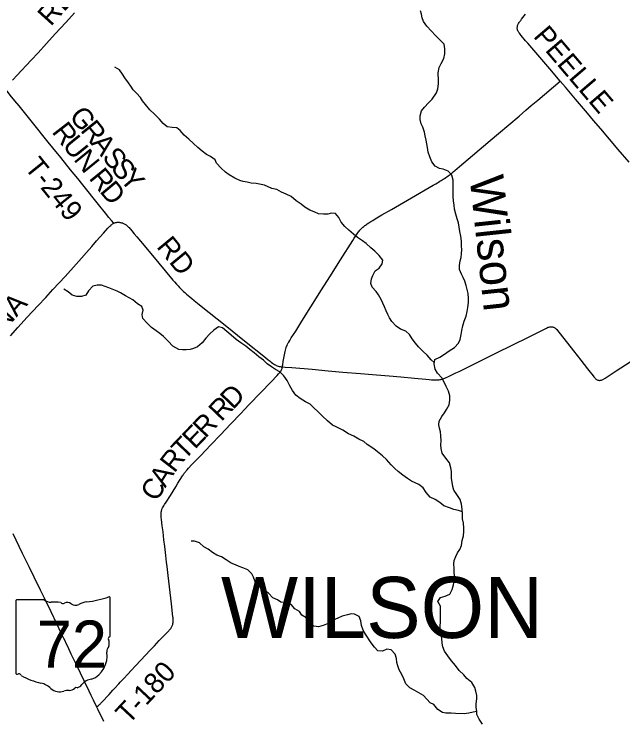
# Model space of a CAD drawing. Extents: x 1442749 to 1756758, y 235267 to 677782.
# Drawn here: x 1630533 to 1639504, y 554957 to 565368 of the extents above; entities that cross this region are included whole.
import ezdxf

# ---------------------------------------------------------------- set-up
doc = ezdxf.new("R2010")
doc.units = 0
for name, color, linetype in [('GM_X_County_Road', 7, 'Continuous'), ('GM_X_County_Road_Text', 7, 'Continuous'), ('GM_X_Minor_River', 7, 'Continuous'), ('GM_X_Minor_River_Text', 7, 'Continuous'), ('GM_X_State_Location', 7, 'Continuous'), ('GM_X_State_Route', 7, 'Continuous'), ('GM_X_State_Shield', 7, 'Continuous'), ('GM_X_Township_Road', 7, 'Continuous'), ('GM_X_Township_Road_Text', 7, 'Continuous'), ('GM_X_Township_Text', 7, 'Continuous')]:
    doc.layers.add(name, color=color, linetype=linetype)

msp = doc.modelspace()

# ---------------------------------------------------------------- linework, layer by layer
at = {"layer": 'GM_X_County_Road'}
for points in [[(1630480, 560630), (1630587, 560750), (1630725, 560902), (1630885, 561075), (1630998, 561196), (1631105, 561312), (1631283, 561503), (1631447, 561687), (1631676, 561946), (1631748, 562027), (1631851, 562143), (1631916, 562214), (1631936, 562236), (1631945, 562246), (1631956, 562256), (1631964, 562263), (1631973, 562271), (1631982, 562278), (1631991, 562283), (1632000, 562288)], [(1632000, 562288), (1632009, 562292), (1632018, 562296), (1632029, 562298), (1632040, 562300), (1632053, 562302), (1632066, 562302), (1632080, 562302), (1632092, 562300), (1632104, 562299), (1632117, 562296), (1632128, 562292), (1632137, 562289), (1632146, 562286), (1632155, 562281), (1632165, 562276), (1632174, 562270), (1632184, 562263), (1632191, 562257), (1632199, 562250), (1632209, 562241), (1632218, 562232), (1632227, 562223), (1632237, 562212), (1632247, 562201), (1632267, 562177), (1632303, 562134), (1632341, 562089), (1632395, 562024), (1632546, 561842), (1632665, 561698), (1632854, 561472), (1632874, 561449), (1632896, 561424), (1632926, 561390), (1632949, 561364), (1632970, 561342), (1632990, 561321), (1633007, 561304), (1633028, 561284), (1633048, 561266), (1633073, 561244), (1633098, 561224), (1633122, 561203), (1633151, 561180), (1633187, 561151), (1633234, 561112), (1633291, 561067), (1633645, 560785), (1633929, 560557), (1634236, 560310), (1634278, 560275), (1634304, 560254), (1634321, 560241), (1634340, 560227), (1634355, 560217), (1634370, 560207), (1634384, 560200), (1634397, 560194), (1634411, 560188), (1634426, 560183), (1634438, 560179), (1634453, 560176), (1634470, 560174), (1634485, 560172)], [(1634485, 560172), (1634528, 560168), (1634627, 560161), (1634925, 560136), (1635160, 560115), (1635379, 560096), (1635635, 560075), (1635873, 560055), (1636062, 560038), (1636232, 560024), (1636432, 560007), (1636598, 559991), (1636651, 559986), (1636684, 559982), (1636709, 559980), (1636731, 559979), (1636750, 559979), (1636766, 559979), (1636781, 559980), (1636798, 559982), (1636812, 559985), (1636823, 559987), (1636837, 559991), (1636849, 559995), (1636863, 560000), (1636880, 560007), (1636900, 560016), (1636925, 560027), (1636956, 560041), (1636994, 560059), (1637042, 560082), (1637091, 560106), (1637150, 560135), (1637305, 560211), (1637640, 560380), (1638112, 560611), (1638377, 560744), (1638392, 560751), (1638404, 560756), (1638415, 560759), (1638428, 560762), (1638438, 560763), (1638449, 560763), (1638458, 560763), (1638468, 560761), (1638478, 560758), (1638487, 560755), (1638493, 560752), (1638500, 560748), (1638507, 560743), (1638515, 560737), (1638523, 560729), (1638530, 560721), (1638542, 560709), (1638562, 560684), (1638634, 560590), (1638777, 560406), (1638885, 560270), (1638982, 560145), (1639004, 560117), (1639064, 560039), (1639075, 560026), (1639085, 560013), (1639094, 560004), (1639101, 559997), (1639108, 559991), (1639117, 559985), (1639125, 559981), (1639133, 559977), (1639141, 559975), (1639148, 559974), (1639158, 559973), (1639166, 559973), (1639174, 559974), (1639181, 559976), (1639191, 559978), (1639200, 559982), (1639207, 559986), (1639216, 559991), (1639226, 559997), (1639234, 560002), (1639242, 560007), (1639403, 560111), (1639679, 560290)]]:
    msp.add_lwpolyline(points, dxfattribs=at)
at = {"layer": 'GM_X_Minor_River'}
for points in [[(1636789, 564392), (1636782, 564504), (1636799, 564584), (1636826, 564640), (1636867, 564712), (1636880, 564782), (1636878, 564855), (1636869, 564925), (1636805, 564988), (1636742, 565053), (1636678, 565122), (1636614, 565189), (1636565, 565261), (1636547, 565312), (1636536, 565366), (1636522, 565418)], [(1636724, 560234), (1636679, 560276), (1636621, 560345), (1636562, 560400), (1636494, 560467), (1636450, 560521), (1636401, 560586), (1636357, 560649), (1636305, 560697), (1636229, 560728), (1636161, 560773), (1636097, 560842), (1636066, 560892), (1636038, 560943), (1636017, 560999), (1635991, 561056), (1635966, 561112), (1635942, 561163), (1635904, 561231), (1635867, 561282), (1635807, 561347), (1635791, 561401), (1635800, 561467), (1635821, 561519), (1635854, 561585), (1635910, 561625), (1635959, 561691), (1635968, 561745), (1635912, 561814), (1635849, 561874), (1635789, 561925), (1635721, 561990), (1635665, 562027), (1635595, 562076), (1635535, 562126), (1635464, 562185), (1635404, 562240), (1635354, 562303), (1635319, 562371), (1635267, 562430), (1635211, 562435), (1635158, 562423), (1635090, 562422), (1635016, 562428), (1634956, 562457), (1634891, 562480), (1634817, 562525), (1634762, 562571), (1634690, 562616), (1634614, 562683), (1634544, 562714), (1634472, 562745), (1634402, 562784), (1634330, 562798), (1634275, 562823), (1634225, 562847), (1634151, 562862), (1634099, 562871), (1634025, 562879), (1633968, 562892), (1633910, 562903), (1633858, 562917), (1633784, 562954), (1633704, 563003), (1633650, 563042), (1633582, 563100), (1633517, 563171), (1633495, 563224), (1633425, 563273), (1633369, 563299), (1633303, 563350), (1633238, 563405), (1633174, 563464), (1633108, 563525), (1633038, 563586), (1632981, 563652), (1632929, 563691), (1632861, 563696), (1632790, 563708), (1632728, 563755), (1632675, 563822), (1632601, 563893), (1632535, 563960), (1632468, 564035), (1632424, 564089), (1632394, 564140), (1632337, 564203), (1632289, 564255), (1632255, 564306), (1632220, 564358), (1632166, 564429), (1632132, 564482), (1632085, 564546), (1632017, 564585)], [(1637124, 558150), (1637108, 558216), (1637055, 558291), (1637013, 558354), (1637000, 558410), (1636986, 558474), (1636979, 558529), (1636979, 558579), (1636978, 558633), (1636968, 558687), (1636949, 558760), (1636896, 558828), (1636842, 558899), (1636827, 558970), (1636821, 559022), (1636826, 559084), (1636820, 559154), (1636817, 559213), (1636803, 559269), (1636790, 559319), (1636798, 559372), (1636837, 559441), (1636876, 559493), (1636903, 559545), (1636942, 559613), (1636954, 559681), (1636955, 559746), (1636936, 559812), (1636902, 559881), (1636865, 559955), (1636835, 560010), (1636771, 560079), (1636736, 560139), (1636721, 560216), (1636733, 560280), (1636804, 560317), (1636877, 560361), (1636946, 560408), (1637023, 560458), (1637082, 560519), (1637108, 560575), (1637123, 560650), (1637132, 560710), (1637147, 560776), (1637163, 560846), (1637192, 560918), (1637209, 560986), (1637220, 561048), (1637227, 561118), (1637231, 561179), (1637222, 561253), (1637210, 561313), (1637195, 561370), (1637175, 561432), (1637150, 561489), (1637124, 561539), (1637097, 561606), (1637095, 561666), (1637108, 561732), (1637119, 561784), (1637127, 561840), (1637132, 561898), (1637128, 561957), (1637125, 562023), (1637118, 562099), (1637100, 562168), (1637091, 562228), (1637080, 562292), (1637060, 562351), (1637041, 562423), (1637021, 562494), (1637016, 562554), (1637006, 562616), (1637003, 562683), (1637005, 562853), (1637004, 562924), (1636982, 562994), (1636928, 563055), (1636856, 563082), (1636802, 563094), (1636740, 563127), (1636687, 563192), (1636657, 563264), (1636636, 563333), (1636624, 563405), (1636615, 563457), (1636605, 563512), (1636592, 563576), (1636578, 563629), (1636555, 563701), (1636533, 563753), (1636516, 563816), (1636516, 563870), (1636537, 563944), (1636578, 563998), (1636637, 564062), (1636694, 564115), (1636757, 564207), (1636776, 564267), (1636787, 564341), (1636789, 564392)], [(1637138, 558035), (1637079, 558058), (1637013, 558072), (1636948, 558095), (1636866, 558126), (1636806, 558175), (1636736, 558216), (1636666, 558254), (1636603, 558319), (1636561, 558392), (1636495, 558439), (1636443, 558463), (1636389, 558488), (1636331, 558529), (1636263, 558577), (1636194, 558632), (1636142, 558673), (1636090, 558730), (1636022, 558807), (1635961, 558863), (1635889, 558920), (1635833, 558963), (1635737, 559030), (1635685, 559071), (1635611, 559106), (1635537, 559151), (1635461, 559187), (1635379, 559238), (1635327, 559265), (1635277, 559287), (1635225, 559312), (1635153, 559379), (1635078, 559448), (1635008, 559515), (1634950, 559568), (1634894, 559620), (1634826, 559657), (1634747, 559704), (1634683, 559755), (1634635, 559824), (1634594, 559894), (1634556, 559971), (1634507, 560038), (1634449, 560098), (1634387, 560135), (1634325, 560174), (1634263, 560219), (1634207, 560269), (1634141, 560322), (1634068, 560381), (1634006, 560430), (1633950, 560477), (1633874, 560524), (1633804, 560574), (1633732, 560639), (1633667, 560694), (1633605, 560745), (1633543, 560760), (1633478, 560714), (1633419, 560658), (1633358, 560595), (1633303, 560527), (1633236, 560469), (1633177, 560442), (1633127, 560428), (1633066, 560421), (1633012, 560421), (1632960, 560428), (1632874, 560477), (1632804, 560552), (1632733, 560617), (1632681, 560663), (1632627, 560704), (1632557, 560751), (1632495, 560816), (1632432, 560886), (1632418, 560943), (1632433, 561009), (1632415, 561059), (1632351, 561100), (1632282, 561161), (1632228, 561190), (1632172, 561220), (1632102, 561261), (1632052, 561288), (1631978, 561316), (1631927, 561337), (1631875, 561357), (1631823, 561374), (1631755, 561373), (1631692, 561359), (1631631, 561293), (1631592, 561226), (1631526, 561206), (1631456, 561207), (1631387, 561230), (1631330, 561276), (1631266, 561317)], [(1637433, 554910), (1637385, 554981), (1637354, 555049), (1637350, 555100), (1637343, 555154), (1637343, 555206), (1637350, 555280), (1637353, 555331), (1637337, 555397), (1637320, 555447), (1637276, 555520), (1637204, 555583), (1637161, 555634), (1637089, 555700), (1637039, 555775), (1636978, 555842), (1636926, 555913), (1636877, 555986), (1636851, 556050), (1636842, 556104), (1636838, 556175), (1636825, 556225), (1636809, 556299), (1636810, 556356), (1636815, 556410), (1636817, 556472), (1636814, 556532), (1636815, 556649), (1636777, 556715), (1636816, 556773), (1636887, 556793), (1636954, 556822), (1636990, 556892), (1637009, 556960), (1637018, 557018), (1637021, 557093), (1637017, 557149), (1637016, 557205), (1637012, 557267), (1637017, 557319), (1637040, 557377), (1637068, 557431), (1637103, 557483), (1637128, 557541), (1637135, 557613), (1637155, 557684), (1637158, 557748), (1637161, 557798), (1637155, 557868), (1637142, 557935), (1637141, 558005), (1637135, 558075), (1637124, 558150)], [(1637351, 555094), (1637300, 555086), (1637233, 555069), (1637163, 555063), (1637038, 555064), (1636974, 555069), (1636897, 555072), (1636847, 555080), (1636775, 555127), (1636718, 555196), (1636666, 555221), (1636614, 555277), (1636566, 555330), (1636496, 555371), (1636428, 555410), (1636362, 555442), (1636305, 555503), (1636277, 555576), (1636248, 555642), (1636206, 555711), (1636189, 555767), (1636175, 555819), (1636166, 555874), (1636146, 555940), (1636088, 556003), (1636026, 556012), (1635960, 555982), (1635893, 555987), (1635843, 556043), (1635794, 556108), (1635711, 556235), (1635679, 556292), (1635650, 556361), (1635644, 556429), (1635617, 556497), (1635549, 556530), (1635499, 556533), (1635446, 556521), (1635369, 556500), (1635305, 556470), (1635236, 556439), (1635159, 556391), (1635085, 556362), (1635018, 556342), (1634948, 556351), (1634884, 556418), (1634830, 556479), (1634772, 556515), (1634739, 556566), (1634671, 556607), (1634615, 556671), (1634537, 556696), (1634465, 556707), (1634413, 556738), (1634343, 556772), (1634283, 556837), (1634209, 556888), (1634129, 556949), (1634080, 557020), (1634062, 557072), (1634038, 557125), (1633975, 557181), (1633901, 557212), (1633848, 557233), (1633796, 557255), (1633732, 557282), (1633660, 557331), (1633591, 557374), (1633522, 557398), (1633454, 557437), (1633393, 557486), (1633329, 557523), (1633263, 557578), (1633191, 557606), (1633140, 557605)]]:
    msp.add_lwpolyline(points, dxfattribs=at)
at = {"layer": 'GM_X_State_Route'}
msp.add_lwpolyline([(1631855, 554948), (1631766, 555131), (1631749, 555167), (1631703, 555261), (1631670, 555329), (1631639, 555394), (1631511, 555660), (1631443, 555802), (1631376, 555941), (1631323, 556053), (1631301, 556098), (1631283, 556135), (1631267, 556169), (1631232, 556240), (1631163, 556385), (1631078, 556562), (1630980, 556763), (1630922, 556881), (1630829, 557072), (1630760, 557217), (1630658, 557423), (1630607, 557526), (1630520, 557710)], dxfattribs=at)
at = {"layer": 'GM_X_State_Shield'}
for p, q in [((1631948, 556213), (1631948, 556765)), ((1630556, 556721), (1630556, 555664)), ((1630978, 556739), (1630570, 556739)), ((1631948, 556213), (1631948, 556213))]:
    msp.add_line(p, q, dxfattribs=at)
for centre, radius, start, end in [((1631452, 558180), 1476, 275.8445, 288.9065), ((1631933, 556768), 15.5, 351.8621, 97.738), ((1630572, 556723), 16.1, 98.1301, 188.1301), ((1631075, 556862), 156, 231.6195, 271.1119), ((1631126, 556146), 562, 80.4867, 94.9883), ((1631254, 556729), 45.1, 219.7921, 297.1024), ((1631320, 556607), 93.8, 54.4667, 119.1411), ((1631441, 556774), 113, 233.8562, 294.8282), ((1631641, 556417), 297, 97.3462, 120.7689), ((1631945, 556172), 24, 107.944, 210.337), ((1631792, 556102), 144, 340.033, 23.6496), ((1631932, 556211), 16.6, 289.6038, 7.7341), ((1632004, 555981), 105, 136.8065, 186.9296), ((1631535, 555911), 369, 292.3089, 8.9858), ((1630572, 555662), 16.3, 171.9584, 258.3066), ((1630575, 555770), 124, 267.339, 280.6039), ((1630600, 555604), 44.8, 29.7484, 93.2717), ((1631165, 556553), 1066, 240.4129, 257.1985), ((1631691, 555368), 202, 94.4031, 142.5768), ((1630847, 555190), 334, 47.1842, 75.836), ((1631208, 555598), 212, 230.7004, 286.2918), ((1631346, 555519), 113, 268.777, 315.5493), ((1631448, 555417), 31.8, 65.7517, 132.6484), ((1631435, 555562), 119, 282.8732, 323.2771), ((1631331, 555233), 174, 85.6951, 111.2099)]:
    msp.add_arc(centre, radius, start, end, dxfattribs=at)
at = {"layer": 'GM_X_Township_Road'}
for points in [[(1630510, 564395), (1630520, 564404), (1630574, 564462), (1630783, 564688), (1630885, 564799), (1631010, 564934), (1631140, 565077), (1631293, 565244), (1631423, 565387)], [(1638582, 564380), (1638527, 564442), (1638455, 564527), (1638103, 564938), (1638071, 564976), (1638003, 565055), (1637988, 565073), (1637978, 565086), (1637971, 565095), (1637965, 565105), (1637960, 565112), (1637957, 565120), (1637954, 565125), (1637952, 565132), (1637950, 565140), (1637949, 565147), (1637948, 565155), (1637947, 565164), (1637948, 565172), (1637949, 565182), (1637950, 565189), (1637953, 565200), (1637957, 565210), (1637961, 565219), (1637967, 565230), (1637975, 565243), (1637981, 565253), (1637988, 565263), (1637998, 565276), (1638010, 565292), (1638029, 565316), (1638071, 565369)], [(1634485, 560172), (1634491, 560204), (1634499, 560250), (1634516, 560350), (1634521, 560375), (1634526, 560398), (1634532, 560419), (1634537, 560439), (1634543, 560456), (1634549, 560471), (1634555, 560487), (1634563, 560504), (1634573, 560524), (1634582, 560538), (1634594, 560559), (1634606, 560579), (1634618, 560598), (1634683, 560700), (1634774, 560845), (1634907, 561055), (1635065, 561305), (1635185, 561497), (1635342, 561747), (1635522, 562033), (1635545, 562068), (1635565, 562099), (1635578, 562118), (1635587, 562131), (1635598, 562147), (1635607, 562159), (1635618, 562172), (1635628, 562184), (1635637, 562194), (1635647, 562205), (1635657, 562215), (1635671, 562228), (1635686, 562240), (1635701, 562252), (1635711, 562260), (1635724, 562269), (1635737, 562278), (1635762, 562295), (1635789, 562312), (1635818, 562330), (1635854, 562352), (1635952, 562409), (1636094, 562492), (1636448, 562698), (1636650, 562815), (1636706, 562848), (1636746, 562870), (1636772, 562885), (1636788, 562895), (1636806, 562905), (1636826, 562917), (1636842, 562927), (1636856, 562936), (1636876, 562949), (1636893, 562961), (1636910, 562973), (1636927, 562985), (1636943, 562997), (1636957, 563007), (1636971, 563019), (1636987, 563031), (1637005, 563046), (1637028, 563066), (1637095, 563123), (1637287, 563286), (1637547, 563508), (1637669, 563612), (1637973, 563867), (1638073, 563952), (1638153, 564020), (1638251, 564102), (1638582, 564380)], [(1639595, 563188), (1639434, 563375), (1639305, 563527), (1639178, 563677), (1639072, 563803), (1638980, 563910), (1638806, 564115), (1638658, 564291), (1638582, 564380)], [(1632000, 562288), (1631967, 562330), (1631931, 562373), (1631882, 562434), (1631776, 562564), (1631544, 562853), (1631470, 562945), (1631366, 563076), (1631221, 563254), (1631103, 563400), (1631037, 563481), (1630996, 563533), (1630844, 563722), (1630606, 564015), (1630544, 564092), (1630476, 564175), (1630434, 564227), (1630424, 564239), (1630416, 564248), (1630407, 564257), (1630395, 564269)], [(1631749, 555167), (1631763, 555176), (1631775, 555184), (1631783, 555190), (1631791, 555197), (1631799, 555204), (1631806, 555212), (1631826, 555233), (1631934, 555348), (1631989, 555409), (1632014, 555435), (1632076, 555503), (1632096, 555525), (1632138, 555571), (1632212, 555649), (1632254, 555695), (1632329, 555774), (1632467, 555923), (1632537, 555997), (1632600, 556063), (1632672, 556139), (1632768, 556239), (1632782, 556254), (1632811, 556284), (1632819, 556293), (1632828, 556303), (1632836, 556312), (1632841, 556319), (1632849, 556330), (1632854, 556339), (1632859, 556348), (1632863, 556357), (1632867, 556368), (1632870, 556377), (1632872, 556386), (1632874, 556395), (1632875, 556402), (1632876, 556414), (1632877, 556428), (1632877, 556441), (1632876, 556456), (1632875, 556473), (1632873, 556489), (1632850, 556681), (1632802, 557098), (1632787, 557229), (1632780, 557294), (1632769, 557392), (1632753, 557525), (1632741, 557626), (1632727, 557743), (1632716, 557831), (1632704, 557925), (1632701, 557955), (1632699, 557971), (1632698, 557990), (1632698, 558003), (1632699, 558019), (1632701, 558033), (1632703, 558045), (1632705, 558054), (1632708, 558064), (1632712, 558074), (1632716, 558084), (1632722, 558096), (1632729, 558109), (1632737, 558124), (1632751, 558146), (1632772, 558180), (1632835, 558279), (1632915, 558407), (1632946, 558457), (1633014, 558566), (1633022, 558578), (1633030, 558589), (1633038, 558601), (1633046, 558612), (1633055, 558623), (1633062, 558632), (1633070, 558642), (1633076, 558649), (1633083, 558657), (1633102, 558679), (1633153, 558734), (1633284, 558868), (1633429, 559019), (1633581, 559178), (1633721, 559326), (1633877, 559490), (1633925, 559539), (1634002, 559620), (1634322, 559953), (1634408, 560045), (1634431, 560069), (1634443, 560083), (1634450, 560092), (1634457, 560100), (1634462, 560108), (1634467, 560115), (1634470, 560122), (1634474, 560130), (1634477, 560137), (1634481, 560148), (1634483, 560159), (1634485, 560172)]]:
    msp.add_lwpolyline(points, dxfattribs=at)

# ---------------------------------------------------------------- texts
at = {"layer": 'GM_X_County_Road_Text'}
for s, rotation, p in [('RD', 309.4965, (1632621, 561939)), ('SABINA', 48.108, (1629763, 560000))]:
    msp.add_text(s, height=300, rotation=rotation, dxfattribs=at).set_placement(p)
at = {"layer": 'GM_X_Minor_River_Text'}
msp.add_text('Wilson', height=500, rotation=276.1253, dxfattribs=at).set_placement((1637244, 562968))
at = {"layer": 'GM_X_State_Location'}
msp.add_text('72', height=1, rotation=0, dxfattribs=at).set_placement((1630985, 556050))
for s in ['s', 'r']:
    msp.add_text(s, height=1, dxfattribs=at).set_placement((1631236, 556123))
at = {"layer": 'GM_X_State_Shield'}
msp.add_text('72', height=696.1, dxfattribs=at).set_placement((1630867, 555739))
at = {"layer": 'GM_X_Township_Road_Text'}
for s, rotation, p in [('RD', 47.7597, (1631073, 565178)), ('PEELLE', 310.4365, (1638173, 565037)), ('G', 308.8783, (1631333, 563859)), ('R', 307.7333, (1631079, 563631)), ('R', 308.8701, (1631499, 563653)), ('U', 308.9926, (1631234, 563430)), ('A', 308.8781, (1631654, 563462)), ('N', 309.0599, (1631400, 563225)), ('S', 308.8735, (1631819, 563256)), ('T-249', 308.8383, (1630674, 563108)), ('S', 308.8742, (1631946, 563098)), ('Y', 310.2423, (1632078, 562935)), ('R', 309.1484, (1631625, 562948)), ('D', 309.911, (1631783, 562753)), ('D', 46.1567, (1633757, 559532)), ('R', 46.1519, (1633586, 559355)), ('R', 46.1574, (1633351, 559110)), ('E', 46.1547, (1633196, 558948)), ('T', 46.3001, (1633041, 558786)), ('R', 52.2558, (1632895, 558598)), ('A', 57.9267, (1632760, 558381)), ('C', 58.0864, (1632630, 558172)), ('T-180', 46.9389, (1632220, 554894))]:
    msp.add_text(s, height=300, rotation=rotation, dxfattribs=at).set_placement(p)
at = {"layer": 'GM_X_Township_Text'}
msp.add_text('WILSON', height=900, rotation=0, dxfattribs=at).set_placement((1633581, 556178))

doc.saveas('drawing.dxf')
